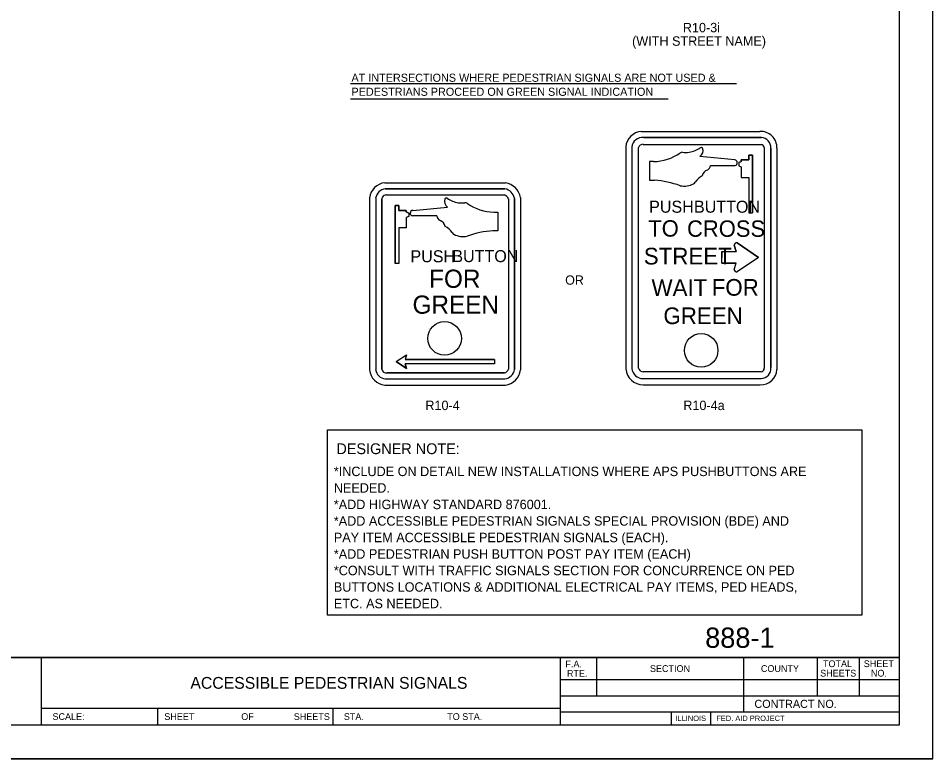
# Model space of a CAD drawing. Extents: x 1896459 to 1901611, y 1616229 to 1617416.
# Drawn here: x 1897481 to 1898159, y 1616316 to 1616866 of the extents above; entities that cross this region are included whole.
import ezdxf

# ---------------------------------------------------------------- set-up
doc = ezdxf.new("R2010")
doc.units = 0
for name, color, linetype in [('Level 1', 7, 'Continuous'), ('Level 8', 7, 'Continuous'), ('ROW_PR_Notes', 7, 'Continuous'), ('Sheets_General Details', 7, 'Continuous')]:
    doc.layers.add(name, color=color, linetype=linetype)

msp = doc.modelspace()

# ---------------------------------------------------------------- linework, layer by layer
at = {"layer": 'Level 1'}
for p, q in [((1897710.22, 1616422.97), (1897710.22, 1616560.3)), ((1897710.22, 1616560.3), (1898106.55, 1616560.3)), ((1898106.55, 1616560.3), (1898106.55, 1616422.97)), ((1898106.55, 1616422.97), (1897710.22, 1616422.97))]:
    msp.add_line(p, q, dxfattribs=at)
at = {"layer": 'ROW_PR_Notes'}
for p, q in [((1897943, 1616781.7), (1898030.73, 1616781.7)), ((1897944.42, 1616772.13), (1898031.78, 1616772.13)), ((1898032.01, 1616777.2), (1897944.71, 1616777.2)), ((1897944.71, 1616777.2), (1898032.01, 1616777.2)), ((1897931.35, 1616770.39), (1897931.35, 1616605.53)), ((1897935.85, 1616770.13), (1897935.85, 1616605.8)), ((1897935.85, 1616770.13), (1897935.85, 1616605.8)), ((1897940.9, 1616606.23), (1897940.9, 1616769.71)), ((1898022.63, 1616760.62), (1898022.63, 1616764.12)), ((1898022.63, 1616764.12), (1898025.3, 1616764.12)), ((1898025.3, 1616764.12), (1898022.63, 1616764.12)), ((1898022.63, 1616764.12), (1898022.63, 1616760.62)), ((1898025.3, 1616764.12), (1898025.3, 1616721.32)), ((1898025.3, 1616721.32), (1898025.3, 1616764.12)), ((1898034.02, 1616769.71), (1898034.02, 1616606.23)), ((1898039.07, 1616606.5), (1898039.07, 1616769.36)), ((1898039.07, 1616769.36), (1898039.07, 1616606.5)), ((1898043.57, 1616769.3), (1898043.57, 1616605.08)), ((1897952.06, 1616759.29), (1897949.07, 1616759.29)), ((1897952.06, 1616759.29), (1897949.07, 1616759.29)), ((1898012.21, 1616760.63), (1897986.32, 1616763.02)), ((1898012.21, 1616760.63), (1897986.32, 1616763.02)), ((1898015.19, 1616758.62), (1898017.02, 1616759.41)), ((1898017.02, 1616759.41), (1898015.19, 1616758.62)), ((1898015.19, 1616758.62), (1898015.19, 1616756.2)), ((1898015.19, 1616758.62), (1898015.19, 1616756.2)), ((1897994.26, 1616756.46), (1898012.49, 1616756.46)), ((1897994.26, 1616756.46), (1898012.49, 1616756.46)), ((1898015.19, 1616756.2), (1898017.02, 1616755.41)), ((1898015.19, 1616756.2), (1898017.02, 1616755.41)), ((1898017.02, 1616755.41), (1898017.02, 1616747.58)), ((1898017.02, 1616755.41), (1898017.02, 1616747.58)), ((1897752.66, 1616743.65), (1897842.26, 1616743.65)), ((1898017.02, 1616747.58), (1898022.63, 1616747.58)), ((1898017.02, 1616747.58), (1898022.63, 1616747.58)), ((1898022.63, 1616747.58), (1898022.63, 1616721.32)), ((1898022.63, 1616747.58), (1898022.63, 1616721.32)), ((1897752.96, 1616739.15), (1897841.81, 1616739.15)), ((1897841.81, 1616739.15), (1897752.96, 1616739.15)), ((1897741.42, 1616732.53), (1897741.42, 1616604.83)), ((1897745.92, 1616732.2), (1897745.92, 1616605.08)), ((1897745.92, 1616732.2), (1897745.92, 1616605.08)), ((1897750.42, 1616731.76), (1897750.42, 1616605.42)), ((1897750.42, 1616605.42), (1897750.42, 1616731.76)), ((1897753.37, 1616734.65), (1897841.24, 1616734.65)), ((1897753.37, 1616734.65), (1897841.24, 1616734.65)), ((1897844.36, 1616731.59), (1897844.36, 1616605.5)), ((1897844.36, 1616731.59), (1897844.36, 1616605.5)), ((1897848.86, 1616732.2), (1897848.86, 1616605.08)), ((1897848.86, 1616605.08), (1897848.86, 1616732.2)), ((1897853.36, 1616732.67), (1897853.36, 1616604.77)), ((1897762.98, 1616726.66), (1897760.32, 1616726.66)), ((1897760.32, 1616726.66), (1897760.32, 1616683.85)), ((1897760.32, 1616683.85), (1897760.32, 1616726.66)), ((1897760.32, 1616726.66), (1897762.98, 1616726.66)), ((1897762.98, 1616723.16), (1897762.98, 1616726.66)), ((1897762.98, 1616726.66), (1897762.98, 1616723.16)), ((1897773.4, 1616723.17), (1897799.29, 1616725.55)), ((1897773.4, 1616723.17), (1897799.29, 1616725.55)), ((1897770.42, 1616721.15), (1897768.6, 1616721.95)), ((1897768.6, 1616721.95), (1897770.42, 1616721.15)), ((1897770.42, 1616718.73), (1897768.6, 1616717.94)), ((1897770.42, 1616718.73), (1897768.6, 1616717.94)), ((1897768.6, 1616717.94), (1897768.6, 1616710.12)), ((1897768.6, 1616717.94), (1897768.6, 1616710.12)), ((1897770.42, 1616721.15), (1897770.42, 1616718.73)), ((1897770.42, 1616721.15), (1897770.42, 1616718.73)), ((1897791.36, 1616719), (1897773.12, 1616719)), ((1897791.36, 1616719), (1897773.12, 1616719)), ((1897833.55, 1616721.83), (1897836.54, 1616721.83)), ((1897833.55, 1616721.83), (1897836.54, 1616721.83)), ((1898022.63, 1616721.32), (1898025.3, 1616721.32)), ((1898022.63, 1616721.32), (1898025.3, 1616721.32)), ((1897768.6, 1616710.12), (1897762.98, 1616710.12)), ((1897762.98, 1616710.12), (1897762.98, 1616683.85)), ((1897768.6, 1616710.12), (1897762.98, 1616710.12)), ((1897762.98, 1616710.12), (1897762.98, 1616683.85)), ((1898011.83, 1616697.45), (1898013.38, 1616692.56)), ((1898013.38, 1616692.56), (1898011.83, 1616697.45)), ((1898029.75, 1616688.32), (1898013.97, 1616699.07)), ((1898013.97, 1616699.07), (1898029.75, 1616688.32)), ((1898002.71, 1616692.56), (1898002.71, 1616688.32)), ((1898002.71, 1616692.56), (1898013.38, 1616692.56)), ((1898002.71, 1616688.32), (1898002.71, 1616692.56)), ((1898002.71, 1616692.56), (1898013.38, 1616692.56)), ((1897762.98, 1616683.85), (1897760.32, 1616683.85)), ((1897762.98, 1616683.85), (1897760.32, 1616683.85)), ((1898002.71, 1616684.08), (1898002.71, 1616688.32)), ((1898002.71, 1616684.08), (1898002.71, 1616688.32)), ((1898002.71, 1616684.08), (1898013.38, 1616684.08)), ((1898013.38, 1616684.08), (1898002.71, 1616684.08)), ((1898011.83, 1616679.2), (1898013.38, 1616684.08)), ((1898011.83, 1616679.2), (1898013.38, 1616684.08)), ((1898029.75, 1616688.32), (1898013.97, 1616677.58)), ((1898029.75, 1616688.32), (1898013.97, 1616677.58)), ((1897761.23, 1616611.02), (1897768.71, 1616616.09)), ((1897761.23, 1616611.02), (1897768.71, 1616616.09)), ((1897768.71, 1616616.09), (1897767.83, 1616612.66)), ((1897768.71, 1616616.09), (1897767.83, 1616612.66)), ((1897761.23, 1616611.02), (1897768.71, 1616605.94)), ((1897768.71, 1616605.94), (1897761.23, 1616611.02)), ((1897833.96, 1616612.66), (1897767.83, 1616612.66)), ((1897767.83, 1616612.66), (1897833.96, 1616612.66)), ((1897768.71, 1616605.94), (1897767.83, 1616609.38)), ((1897833.96, 1616609.38), (1897767.83, 1616609.38)), ((1897767.83, 1616609.38), (1897768.71, 1616605.94)), ((1897833.96, 1616609.38), (1897767.83, 1616609.38)), ((1897833.96, 1616612.66), (1897833.96, 1616609.38)), ((1897833.96, 1616612.66), (1897833.96, 1616609.38)), ((1897754.42, 1616602.63), (1897841.44, 1616602.63)), ((1897841.44, 1616602.63), (1897754.42, 1616602.63)), ((1898031.78, 1616603.44), (1897944.42, 1616603.44)), ((1897752.96, 1616598.13), (1897841.81, 1616598.13)), ((1897752.96, 1616598.13), (1897841.81, 1616598.13)), ((1897944.27, 1616598.37), (1898031.91, 1616598.37)), ((1897944.27, 1616598.37), (1898031.91, 1616598.37)), ((1897752.74, 1616593.63), (1897842.1, 1616593.63)), ((1897944.24, 1616593.87), (1898031.17, 1616593.87))]:
    msp.add_line(p, q, dxfattribs=at)
for points in [[(1897949.07, 1616759.29), (1897949.07, 1616745.55), (1897952.67, 1616745.55)], [(1897949.07, 1616759.29), (1897949.07, 1616745.55), (1897952.67, 1616745.55)], [(1898017.02, 1616759.41), (1898017.02, 1616760.62), (1898022.63, 1616760.62)], [(1898022.63, 1616760.62), (1898017.02, 1616760.62), (1898017.02, 1616759.41)], [(1897768.6, 1616721.95), (1897768.6, 1616723.16), (1897762.98, 1616723.16)], [(1897762.98, 1616723.16), (1897768.6, 1616723.16), (1897768.6, 1616721.95)], [(1897836.54, 1616721.83), (1897836.54, 1616708.08), (1897832.94, 1616708.08)], [(1897836.54, 1616721.83), (1897836.54, 1616708.08), (1897832.94, 1616708.08)]]:
    msp.add_lwpolyline(points, dxfattribs=at)
for centre in [(1897797.02, 1616628.16), (1897987.36, 1616619.28)]:
    msp.add_circle(centre, 12.46, dxfattribs=at)
for centre, radius, start, end in [((1897943.95, 1616769.06), 12.67, 94.29797, 173.98985), ((1898031.44, 1616769.59), 12.13, 358.60548, 93.3759), ((1897943.95, 1616769.06), 8.17, 84.64687, 172.51344), ((1898031.44, 1616769.59), 7.63, 358.24152, 85.74271), ((1897951.42, 1616794.35), 35.07, 271.05873, 305.16386), ((1897951.42, 1616794.35), 35.07, 271.05873, 305.16386), ((1897973.22, 1616763.92), 2.39, 84.4009, 132.28335), ((1897973.22, 1616763.92), 2.39, 84.4009, 132.28335), ((1897975.99, 1616782.47), 16.37, 261.08728, 278.91272), ((1897975.99, 1616782.47), 16.37, 261.08728, 278.91272), ((1897974.58, 1616787.74), 21.8, 280.43816, 303.67886), ((1897983.57, 1616767.4), 5.18, 302.07355, 21.38568), ((1897987.35, 1616768.41), 1.37, 40.11687, 119.85678), ((1898011.99, 1616758.52), 2.12, 283.60632, 84.07349), ((1898011.99, 1616758.52), 2.12, 283.60632, 84.07349), ((1897993.63, 1616747.8), 5.51, 107.34456, 170.38086), ((1897993.63, 1616747.8), 5.51, 107.34456, 170.38086), ((1897989.7, 1616757.05), 4.59, 299.72463, 352.63238), ((1897989.7, 1616757.05), 4.59, 299.72463, 352.63238), ((1897754.23, 1616730.82), 12.93, 96.99238, 172.38954), ((1897839.79, 1616730.05), 13.82, 10.92827, 79.69975), ((1897947.13, 1616672.63), 73.12, 70.27132, 85.65239), ((1897947.13, 1616672.63), 73.12, 70.27132, 85.65239), ((1897980.3, 1616745.45), 2.94, 297.99846, 334.75971), ((1897980.3, 1616745.45), 2.94, 297.99846, 334.75971), ((1897994.48, 1616736.15), 14.05, 116.58495, 145.09554), ((1897994.48, 1616736.15), 14.05, 116.58495, 145.09554), ((1897754.23, 1616730.82), 8.43, 98.66309, 170.57058), ((1897754.23, 1616730.82), 8.43, 98.66309, 170.57058), ((1897839.79, 1616730.05), 9.32, 13.31714, 77.44919), ((1897839.79, 1616730.05), 9.32, 13.31714, 77.44919), ((1897974.78, 1616756.11), 14.94, 258.54288, 297.49398), ((1897974.78, 1616756.11), 14.94, 258.54288, 297.49398), ((1897754.23, 1616730.82), 3.93, 102.70353, 166.1699), ((1897754.23, 1616730.82), 3.93, 102.70353, 166.1699), ((1897802.04, 1616729.94), 5.18, 158.61432, 237.92645), ((1897798.27, 1616730.94), 1.37, 60.14322, 139.88313), ((1897811.04, 1616750.27), 21.8, 236.32114, 259.56184), ((1897839.79, 1616730.05), 4.82, 18.55669, 72.51534), ((1897839.79, 1616730.05), 4.82, 18.55669, 72.51534), ((1897773.62, 1616721.06), 2.12, 95.92651, 256.39368), ((1897773.62, 1616721.06), 2.12, 95.92651, 256.39368), ((1897809.63, 1616745.01), 16.37, 261.08728, 278.91272), ((1897809.63, 1616745.01), 16.37, 261.08728, 278.91272), ((1897812.4, 1616726.46), 2.39, 47.71665, 95.5991), ((1897812.4, 1616726.46), 2.39, 47.71665, 95.5991), ((1897834.2, 1616756.89), 35.07, 234.83614, 268.94127), ((1897834.2, 1616756.89), 35.07, 234.83614, 268.94127), ((1897795.91, 1616719.59), 4.59, 187.36762, 240.27537), ((1897795.91, 1616719.59), 4.59, 187.36762, 240.27537), ((1897791.99, 1616710.33), 5.51, 9.61914, 72.65544), ((1897791.99, 1616710.33), 5.51, 9.61914, 72.65544), ((1897791.14, 1616698.69), 14.05, 34.90446, 63.41505), ((1897791.14, 1616698.69), 14.05, 34.90446, 63.41505), ((1897805.32, 1616707.98), 2.94, 205.24029, 242.00154), ((1897805.32, 1616707.98), 2.94, 205.24029, 242.00154), ((1897810.84, 1616718.64), 14.94, 242.50602, 281.45712), ((1897810.84, 1616718.64), 14.94, 242.50602, 281.45712), ((1897838.49, 1616635.17), 73.12, 94.34761, 109.72868), ((1897838.49, 1616635.17), 73.12, 94.34761, 109.72868), ((1898013.53, 1616697.42), 1.7, 75.17184, 178.9423), ((1898013.53, 1616697.42), 1.7, 75.17184, 178.9423), ((1898013.53, 1616679.23), 1.7, 181.0577, 284.82816), ((1898013.53, 1616679.23), 1.7, 181.0577, 284.82816), ((1897753.84, 1616606.07), 12.49, 185.68043, 264.93209), ((1897753.84, 1616606.07), 7.99, 187.10413, 263.6622), ((1897753.84, 1616606.07), 7.99, 187.10413, 263.6622), ((1897753.84, 1616606.07), 3.49, 190.75994, 279.59762), ((1897753.84, 1616606.07), 3.49, 190.75994, 279.59762), ((1897840.65, 1616606.36), 3.81, 281.90327, 346.96098), ((1897840.65, 1616606.36), 3.81, 281.90327, 346.96098), ((1897840.65, 1616606.36), 8.31, 278.04966, 351.184), ((1897840.65, 1616606.36), 8.31, 278.04966, 351.184), ((1897840.65, 1616606.36), 12.81, 276.48097, 352.90244), ((1897944.37, 1616606.97), 13.1, 186.29715, 269.4347), ((1897944.37, 1616606.97), 8.6, 187.77405, 269.3023), ((1898031.58, 1616605.87), 12.01, 268.01757, 356.22094), ((1898031.58, 1616605.87), 7.51, 272.50715, 4.77971)]:
    msp.add_arc(centre, radius, start, end, dxfattribs=at)
for centre, major_axis, start_param, end_param in [((1897943.94, 1616769.04), (0, 8.19), 6.188693, 7.720886), ((1897943.94, 1616769.04), (0, 3.13), 6.130117, 7.638252), ((1898031.46, 1616769.58), (0, 2.57), 4.762747, 6.15863), ((1898031.46, 1616769.58), (0, 7.64), 4.68318, 6.210965), ((1897944.36, 1616606.99), (0, 8.62), 1.708502, 3.13095), ((1897944.36, 1616606.99), (0, 3.55), 1.78553, 3.15817), ((1898031.6, 1616605.88), (0, 2.45), 3.214566, 4.856018), ((1898031.6, 1616605.88), (0, 7.52), 3.183253, 4.794352)]:
    msp.add_ellipse(centre, major_axis=major_axis, ratio=0.996422, start_param=start_param, end_param=end_param, dxfattribs=at)
at = {"layer": 'Sheets_General Details'}
for p, q in [((1898159.07, 1616316.47), (1898159.07, 1617416.47)), ((1897727.25, 1616817.19), (1898013.43, 1616817.19)), ((1897727.25, 1616805.99), (1897962.86, 1616805.99)), ((1896559.07, 1616391.47), (1898134.07, 1616391.47)), ((1897497.78, 1616391.47), (1897497.78, 1616341.47)), ((1897882.78, 1616391.47), (1897882.78, 1616341.47)), ((1897909.79, 1616391.47), (1897909.79, 1616363.21)), ((1898018.79, 1616391.47), (1898018.79, 1616351.21)), ((1898073.39, 1616391.47), (1898073.39, 1616363.21)), ((1898104.43, 1616391.47), (1898104.43, 1616363.21)), ((1897882.78, 1616375.21), (1898134.07, 1616375.21)), ((1897882.78, 1616363.21), (1898134.07, 1616363.21)), ((1897497.78, 1616353.97), (1897882.78, 1616353.97)), ((1897584.07, 1616353.97), (1897584.07, 1616341.47)), ((1897714.07, 1616353.97), (1897714.07, 1616341.47)), ((1897882.78, 1616351.21), (1898134.07, 1616351.21)), ((1897965.14, 1616351.21), (1897965.14, 1616341.47)), ((1897994.14, 1616351.21), (1897994.14, 1616341.47)), ((1898159.07, 1616316.47), (1896459.07, 1616316.47))]:
    msp.add_line(p, q, dxfattribs=at)
for points in [[(1896459.07, 1616316.47), (1898159.07, 1616316.47), (1898159.07, 1617416.47), (1896459.07, 1617416.47)], [(1896559.07, 1617391.47), (1898134.07, 1617391.47), (1898134.07, 1616341.47), (1896559.07, 1616341.47)], [(1896559.07, 1617391.46), (1898134.07, 1617391.46), (1898134.07, 1616391.47), (1896559.07, 1616391.47)]]:
    msp.add_lwpolyline(points, close=True, dxfattribs=at)

# ---------------------------------------------------------------- texts
at = {"layer": 'Level 1'}
for s, height, p in [('DESIGNER NOTE:', 8, (1897716.78, 1616542.38)), ('*INCLUDE ON DETAIL NEW INSTALLATIONS WHERE APS PUSHBUTTONS ARE ', 7, (1897714.89, 1616526.07)), ('NEEDED.', 7, (1897714.89, 1616513.82)), ('*ADD HIGHWAY STANDARD 876001.', 7, (1897714.89, 1616501.57)), ('*ADD ACCESSIBLE PEDESTRIAN SIGNALS SPECIAL PROVISION (BDE) AND ', 7, (1897714.89, 1616489.32)), ('PAY ITEM ACCESSIBLE PEDESTRIAN SIGNALS (EACH).', 7, (1897714.89, 1616477.07)), ('*ADD PEDESTRIAN PUSH BUTTON POST PAY ITEM (EACH)', 7, (1897714.89, 1616464.82)), ('*CONSULT WITH TRAFFIC SIGNALS SECTION FOR CONCURRENCE ON PED ', 7, (1897714.89, 1616452.57)), ('BUTTONS LOCATIONS & ADDITIONAL ELECTRICAL PAY ITEMS, PED HEADS, ', 7, (1897714.89, 1616440.32)), ('ETC. AS NEEDED.', 7, (1897714.89, 1616428.07)), ('888-1', 15.042, (1897990.31, 1616398.71))]:
    msp.add_text(s, height=height, dxfattribs=at).set_placement(p)
at = {"layer": 'Level 8'}
for s, height, p in [('R10-3i', 7, (1897973.74, 1616855.21)), ('(WITH STREET NAME)', 7, (1897936.1, 1616845.24)), ('AT INTERSECTIONS WHERE PEDESTRIAN SIGNALS ARE NOT USED & ', 6, (1897727.97, 1616818.52)), ('PEDESTRIANS PROCEED ON GREEN SIGNAL INDICATION', 6, (1897727.97, 1616808.12)), ('OR', 6.901, (1897886.49, 1616668.01)), ('R10-4', 7, (1897782.77, 1616575.04)), ('R10-4a', 7, (1897974.08, 1616575.04))]:
    msp.add_text(s, height=height, dxfattribs=at).set_placement(p)
at = {"layer": 'ROW_PR_Notes'}
for s, height, p in [('PUSH', 8.91, (1897948.76, 1616721.41)), ('BUTTON', 8.91, (1897982.03, 1616721.41)), ('TO', 12.176, (1897948.12, 1616703.68)), ('CROSS', 12.176, (1897976.86, 1616703.54)), ('PUSH', 8.91, (1897771.73, 1616684.65)), ('BUTTON', 8.91, (1897802.79, 1616684.77)), ('STREET', 12.377, (1897944.78, 1616683.02)), ('FOR', 13.487, (1897785.56, 1616665.72)), ('WAIT', 12.377, (1897950.51, 1616659.68)), ('FOR', 12.377, (1897995.15, 1616659.85)), ('GREEN', 13.487, (1897773.26, 1616646.5)), ('GREEN', 12.377, (1897959.34, 1616638.78))]:
    msp.add_text(s, height=height, dxfattribs=at).set_placement(p)
at = {"layer": 'Sheets_General Details'}
for s, height, p in [('F.A.  ', 5, (1897886.64, 1616384.22)), ('SECTION', 4.999, (1897949.36, 1616380.83)), ('COUNTY', 4.999, (1898031.65, 1616380.83)), ('TOTAL', 4.999, (1898077.69, 1616384.4)), ('SHEET', 4.999, (1898107.96, 1616384.4)), (' ACCESSIBLE PEDESTRIAN SIGNALS', 8.75, (1897605.25, 1616368.34)), ('RTE.', 5, (1897887.8, 1616377.22)), ('SHEETS', 4.999, (1898075.61, 1616377.4)), ('NO.', 4.999, (1898113.25, 1616377.4)), ('CONTRACT NO.      ', 6, (1898026.84, 1616354.14)), ('SCALE:          ', 5, (1897506.24, 1616345.22)), ('SHEET', 5, (1897589.17, 1616345.22)), ('OF', 5, (1897646.22, 1616345.22)), ('SHEETS', 5, (1897685.17, 1616345.22)), ('STA.', 5, (1897722.32, 1616345.22)), ('TO STA.', 5, (1897798.98, 1616345.22)), ('ILLINOIS', 4, (1897968.23, 1616344.44)), ('FED. AID PROJECT', 4, (1897998.56, 1616344.44))]:
    msp.add_text(s, height=height, dxfattribs=at).set_placement(p)

doc.saveas('drawing.dxf')
